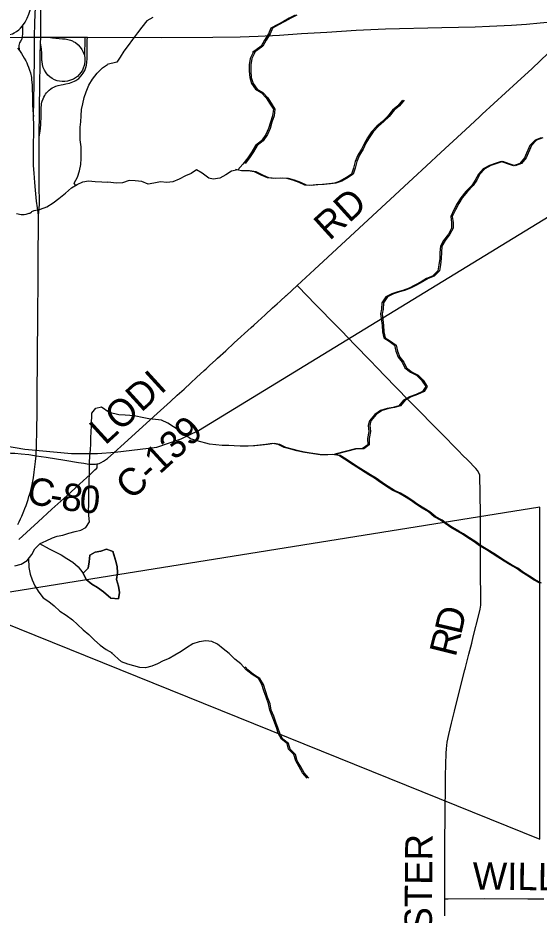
# Model space of a CAD drawing. Extents: x 0 to 34, y 0 to 22.
# Drawn here: x 16.545 to 17.627, y 4.394 to 6.258 of the extents above; entities that cross this region are included whole.
import ezdxf

# ---------------------------------------------------------------- set-up
doc = ezdxf.new("R2010")
doc.units = 0
for name, color, linetype in [('GM_X_County_Road', 7, 'Continuous'), ('GM_X_County_Road_Text', 7, 'Continuous'), ('GM_X_Interchange_Ramps', 7, 'Continuous'), ('GM_X_Minor_Lake', 7, 'Continuous'), ('GM_X_Minor_River', 7, 'Continuous'), ('GM_X_Rail_Line', 7, 'Continuous'), ('GM_X_State_Route', 7, 'Continuous'), ('GM_X_Township_Road', 7, 'Continuous'), ('GM_X_US_Route', 7, 'Continuous'), ('SH_Text', 7, 'Continuous')]:
    doc.layers.add(name, color=color, linetype=linetype)

msp = doc.modelspace()

# ---------------------------------------------------------------- linework, layer by layer
at = {"layer": 'GM_X_County_Road'}
for points in [[(16.7092, 5.3311), (16.7113, 5.3316), (16.7141, 5.3323), (16.7184, 5.334), (16.7231, 5.3366), (16.7312, 5.3422), (16.7447, 5.3541), (16.7661, 5.3736), (16.8274, 5.4295), (16.8621, 5.4611), (16.876, 5.4739), (16.8901, 5.4867), (16.9046, 5.4999), (16.916, 5.5106), (16.9318, 5.5251), (16.936, 5.5289), (16.943, 5.5354), (16.956, 5.5473), (16.9597, 5.5507), (16.9769, 5.5665), (16.9945, 5.5826), (17.0294, 5.6146), (17.0351, 5.6198), (17.0434, 5.6274), (17.0586, 5.6413), (17.0742, 5.6555), (17.0833, 5.6638), (17.0896, 5.6696), (17.1025, 5.6813), (17.1026, 5.6814), (17.1248, 5.7017), (17.1613, 5.7354), (17.328, 5.8895), (17.357, 5.9165), (17.3655, 5.9243), (17.3938, 5.9506), (17.4233, 5.9781), (17.4664, 6.0178), (17.4744, 6.0254), (17.5038, 6.0526), (17.5075, 6.0561), (17.5093, 6.0578), (17.5822, 6.1241), (17.613, 6.153), (17.6461, 6.1845)], [(17.4319, 4.3926), (17.4316, 4.4276), (17.4314, 4.4834), (17.432, 4.5583), (17.4325, 4.5866), (17.4333, 4.6832), (17.4337, 4.7064), (17.4344, 4.7303), (17.4349, 4.7393), (17.4363, 4.7529), (17.4398, 4.7689), (17.4455, 4.7925), (17.4517, 4.8174), (17.4735, 4.9041), (17.4737, 4.9047), (17.4746, 4.908), (17.4818, 4.9362), (17.4875, 4.9587), (17.4909, 4.9721), (17.5022, 5.0177), (17.505, 5.0297), (17.5065, 5.038), (17.5068, 5.0446), (17.5061, 5.113), (17.5059, 5.1526), (17.5055, 5.2282), (17.5043, 5.3077), (17.5022, 5.3124), (17.4995, 5.3175), (17.4964, 5.3214), (17.4794, 5.3388), (17.4687, 5.3495), (17.4609, 5.3577), (17.4533, 5.3654), (17.4303, 5.3888), (17.4132, 5.4063), (17.4, 5.4196), (17.3862, 5.4337), (17.358, 5.4625), (17.3301, 5.4909), (17.3075, 5.5138), (17.291, 5.531), (17.2766, 5.546), (17.2447, 5.5789), (17.217, 5.6077), (17.1973, 5.6275), (17.1735, 5.6518), (17.1612, 5.6647), (17.1475, 5.6788), (17.1248, 5.7017)], [(16.5831, 5.3482), (16.6041, 5.3452), (16.6424, 5.3391), (16.6709, 5.3345), (16.6821, 5.3327), (16.6927, 5.331), (16.6967, 5.3308), (16.7032, 5.3305), (16.7066, 5.3307), (16.7092, 5.3311)], [(17.4316, 4.4276), (17.4386, 4.4276), (17.5145, 4.4286), (17.6039, 4.4277), (17.6373, 4.4274)]]:
    msp.add_lwpolyline(points, dxfattribs=at)
at = {"layer": 'GM_X_Interchange_Ramps'}
for points in [[(16.5548, 6.2413), (16.5546, 6.2336), (16.5544, 6.226), (16.5542, 6.2176)], [(16.5542, 6.2176), (16.5539, 6.2163), (16.5534, 6.215), (16.553, 6.214), (16.5523, 6.2128), (16.5516, 6.2116), (16.5506, 6.2099), (16.5496, 6.2079), (16.5487, 6.2058), (16.548, 6.2036), (16.5474, 6.2006), (16.5474, 6.1987), (16.5474, 6.1966), (16.5478, 6.194), (16.5481, 6.1913), (16.5483, 6.1902)], [(16.5895, 6.01), (16.5915, 6.0226), (16.5925, 6.0357), (16.5934, 6.0549), (16.5938, 6.0727), (16.5941, 6.0761), (16.5945, 6.0797), (16.5952, 6.0827), (16.5958, 6.0852), (16.5976, 6.0899), (16.599, 6.093), (16.6008, 6.0965), (16.6026, 6.0993), (16.6048, 6.1022), (16.6073, 6.1052), (16.6098, 6.1075), (16.6134, 6.1103), (16.6166, 6.1124), (16.6197, 6.114), (16.6242, 6.116), (16.6289, 6.1174), (16.6347, 6.1188), (16.6394, 6.1197), (16.645, 6.1208), (16.6522, 6.1226), (16.656, 6.1238), (16.6594, 6.125), (16.6628, 6.1266), (16.6657, 6.1281), (16.6714, 6.1322), (16.6762, 6.1372), (16.6805, 6.1428), (16.684, 6.1488), (16.6863, 6.1547), (16.6875, 6.1595), (16.6885, 6.1658), (16.6887, 6.1728), (16.6889, 6.1953), (16.6892, 6.2072), (16.6893, 6.2118), (16.6895, 6.2177)], [(16.6841, 6.2176), (16.684, 6.2038), (16.6836, 6.1899), (16.6833, 6.1806)], [(16.5446, 6.195), (16.5483, 6.1902), (16.5525, 6.1838), (16.5554, 6.1793), (16.5585, 6.174), (16.5614, 6.1687), (16.5635, 6.1644), (16.5653, 6.1602), (16.5673, 6.1553), (16.5694, 6.1492), (16.571, 6.1436), (16.5731, 6.1342), (16.5737, 6.1294), (16.5742, 6.1244), (16.5748, 6.1178), (16.5751, 6.1096), (16.5754, 6.0962), (16.5756, 6.0779), (16.5764, 6.0654), (16.5778, 6.0532)]]:
    msp.add_lwpolyline(points, dxfattribs=at)
at = {"layer": 'GM_X_Minor_Lake'}
for points in [[(16.7423, 5.1496), (16.7294, 5.154), (16.7172, 5.1501), (16.7053, 5.1476), (16.6946, 5.1414), (16.6932, 5.1277), (16.6914, 5.1148), (16.6806, 5.1044), (16.6872, 5.0913), (16.6984, 5.0816), (16.7105, 5.0742), (16.7229, 5.0656), (16.7383, 5.0523)], [(16.7373, 5.0532), (16.7229, 5.0656), (16.7105, 5.0742), (16.6984, 5.0816), (16.6872, 5.0913), (16.6806, 5.1044), (16.6914, 5.1148), (16.6932, 5.1277), (16.6946, 5.1414), (16.7053, 5.1476), (16.7172, 5.1501), (16.7294, 5.154), (16.7412, 5.15)], [(16.7422, 5.1498), (16.7481, 5.1313), (16.7515, 5.1184), (16.752, 5.1047), (16.7501, 5.0911), (16.754, 5.077), (16.7559, 5.0641), (16.7541, 5.0512), (16.7377, 5.0524)], [(16.7383, 5.0523), (16.7541, 5.0512), (16.7559, 5.0641), (16.754, 5.077), (16.7501, 5.0911), (16.752, 5.1047), (16.7515, 5.1184), (16.7481, 5.1313), (16.7423, 5.1496)]]:
    msp.add_lwpolyline(points, dxfattribs=at)
at = {"layer": 'GM_X_Minor_River'}
for points in [[(17.1212, 6.2636), (17.1087, 6.2575), (17.0966, 6.2502), (17.0833, 6.2437), (17.0704, 6.2369), (17.0658, 6.2251), (17.0575, 6.2114), (17.0503, 6.1992), (17.0326, 6.1862)], [(17.1245, 6.2636), (17.112, 6.2575), (17.0998, 6.2502), (17.0865, 6.2437), (17.0736, 6.2369), (17.0691, 6.2251), (17.0608, 6.2114), (17.0536, 6.1992), (17.0359, 6.1862)], [(16.8256, 6.259), (16.8127, 6.2521), (16.8025, 6.2384), (16.7934, 6.2266), (16.7828, 6.2133), (16.7741, 6.2007), (16.765, 6.1886), (16.7574, 6.176), (16.7506, 6.1657), (16.7305, 6.161)], [(17.0336, 6.1859), (17.0276, 6.1733), (17.0254, 6.1604), (17.0254, 6.1475), (17.0266, 6.1338), (17.0305, 6.1213), (17.0385, 6.1095), (17.0503, 6.1031), (17.061, 6.0921), (17.0679, 6.0804), (17.0756, 6.0682), (17.0737, 6.0545), (17.0696, 6.0412), (17.0658, 6.0283), (17.0602, 6.0154), (17.0511, 6.0028), (17.0389, 5.9929), (17.031, 5.9796), (17.0227, 5.967), (17.0124, 5.9541), (17.0018, 5.9423), (16.9889, 5.9396), (16.9768, 5.932), (16.9642, 5.9251), (16.9509, 5.9231), (16.9414, 5.9246), (16.9281, 5.9356), (16.9162, 5.9424), (16.9048, 5.9344), (16.8931, 5.9298), (16.8802, 5.9226), (16.8672, 5.9172), (16.8547, 5.9157), (16.8414, 5.9172), (16.8277, 5.9148), (16.8155, 5.9125), (16.8026, 5.9178), (16.7889, 5.9197), (16.7759, 5.92), (16.7626, 5.9154), (16.7497, 5.9146), (16.7321, 5.9163)], [(17.0369, 6.1859), (17.0309, 6.1733), (17.0286, 6.1604), (17.0287, 6.1475), (17.0299, 6.1338), (17.0337, 6.1213), (17.0418, 6.1095), (17.0536, 6.1031), (17.0643, 6.0921), (17.0712, 6.0804), (17.0788, 6.0682), (17.077, 6.0545), (17.0728, 6.0412), (17.0691, 6.0283), (17.0634, 6.0154), (17.0543, 6.0028), (17.0422, 5.9929), (17.0343, 5.9796), (17.0259, 5.967), (17.0169, 5.9556)], [(16.6649, 5.9106), (16.6623, 5.9145), (16.669, 5.9273), (16.6734, 5.9405), (16.6759, 5.9534), (16.6765, 5.9655), (16.6764, 5.9784), (16.6762, 5.9902), (16.6746, 6.0043), (16.6744, 6.0173), (16.6747, 6.0309), (16.6756, 6.0423), (16.6762, 6.0545), (16.6772, 6.0674), (16.6797, 6.0795), (16.6826, 6.0924), (16.6866, 6.1045), (16.6922, 6.118), (16.7004, 6.1308), (16.7098, 6.1428), (16.721, 6.154), (16.7309, 6.1611)], [(17.3437, 6.0872), (17.3343, 6.075), (17.3233, 6.0659), (17.3127, 6.0533), (17.302, 6.0426), (17.2907, 6.0327), (17.2793, 6.0213), (17.2714, 6.0087), (17.2646, 5.9973), (17.2589, 5.9852), (17.2509, 5.973), (17.2457, 5.9593), (17.2419, 5.9456), (17.2382, 5.9331), (17.2275, 5.9262), (17.2146, 5.9189), (17.2025, 5.9143), (17.1911, 5.9132), (17.1777, 5.912), (17.1648, 5.9108), (17.1511, 5.9096), (17.1412, 5.9104), (17.1294, 5.916), (17.1161, 5.9206), (17.1035, 5.9239), (17.0906, 5.9251), (17.0769, 5.9243), (17.0632, 5.9257), (17.0502, 5.931), (17.0365, 5.9378), (17.0228, 5.9401), (17.0098, 5.9404), (16.9969, 5.943)], [(17.347, 6.0872), (17.3375, 6.075), (17.3265, 6.0659), (17.3159, 6.0533), (17.3053, 6.0426), (17.2939, 6.0327), (17.2826, 6.0213), (17.2746, 6.0087), (17.2678, 5.9973), (17.2622, 5.9852), (17.2542, 5.973), (17.2489, 5.9593), (17.2452, 5.9456), (17.2414, 5.9331), (17.2308, 5.9262), (17.2179, 5.9189), (17.2057, 5.9143), (17.1943, 5.9132), (17.181, 5.912), (17.1681, 5.9108), (17.1544, 5.9096), (17.1445, 5.9104), (17.1327, 5.916), (17.1193, 5.9206), (17.1068, 5.9239), (17.0938, 5.9251), (17.0801, 5.9243), (17.0664, 5.9257), (17.0535, 5.931), (17.0397, 5.9378), (17.026, 5.9401), (17.0169, 5.9403)], [(17.6321, 6.0086), (17.6191, 6.0036), (17.6085, 5.9929), (17.5972, 5.9671), (17.5877, 5.9557), (17.5744, 5.9507), (17.5619, 5.9548), (17.5489, 5.9594), (17.5364, 5.9551), (17.5242, 5.9509), (17.5113, 5.9444), (17.5015, 5.9334), (17.495, 5.9205), (17.4875, 5.9094), (17.4753, 5.8972), (17.4647, 5.8843), (17.4575, 5.8721), (17.4507, 5.8592), (17.4439, 5.8455), (17.4455, 5.8326), (17.4456, 5.8208), (17.4391, 5.8086), (17.4293, 5.7953), (17.4225, 5.7835), (17.4214, 5.7702), (17.4211, 5.758), (17.4196, 5.7451), (17.4174, 5.7326), (17.406, 5.7215), (17.3938, 5.7162), (17.3824, 5.7097), (17.3695, 5.7024), (17.3574, 5.6967), (17.3445, 5.6917), (17.3342, 5.6887), (17.3217, 5.6845), (17.3095, 5.6787), (17.3012, 5.6658), (17.3001, 5.6525), (17.2982, 5.643), (17.3014, 5.6187), (17.3022, 5.6058), (17.3049, 5.5929), (17.3159, 5.5864), (17.3274, 5.5777), (17.3301, 5.5652), (17.3347, 5.5531), (17.3431, 5.5428), (17.3485, 5.5307), (17.3607, 5.5216), (17.3729, 5.5156), (17.3832, 5.505), (17.392, 5.4921), (17.3856, 5.4814), (17.3719, 5.4753), (17.3582, 5.4707), (17.3461, 5.4638), (17.3362, 5.4516), (17.3241, 5.4482), (17.3123, 5.4463), (17.2982, 5.4424), (17.2861, 5.4337), (17.2751, 5.4207), (17.2728, 5.4112), (17.274, 5.3983), (17.2714, 5.3842), (17.2715, 5.3709), (17.2601, 5.3629), (17.2464, 5.3629), (17.2033, 5.3513)], [(17.6353, 6.0086), (17.6224, 6.0036), (17.6118, 5.9929), (17.6005, 5.9671), (17.591, 5.9557), (17.5777, 5.9507), (17.5651, 5.9548), (17.5522, 5.9594), (17.5396, 5.9551), (17.5275, 5.9509), (17.5146, 5.9444), (17.5047, 5.9334), (17.4983, 5.9205), (17.4907, 5.9094), (17.4786, 5.8972), (17.468, 5.8843), (17.4608, 5.8721), (17.454, 5.8592), (17.4472, 5.8455), (17.4488, 5.8326), (17.4488, 5.8208), (17.4424, 5.8086), (17.4326, 5.7953), (17.4258, 5.7835), (17.4247, 5.7702), (17.4243, 5.758), (17.4229, 5.7451), (17.4206, 5.7326), (17.4093, 5.7215), (17.3971, 5.7162), (17.3857, 5.7097), (17.3728, 5.7024), (17.3606, 5.6967), (17.3477, 5.6917), (17.3375, 5.6887), (17.3249, 5.6845), (17.3128, 5.6787), (17.3044, 5.6658), (17.3034, 5.6525), (17.3015, 5.643), (17.3046, 5.6187), (17.3054, 5.6058), (17.3081, 5.5929), (17.3192, 5.5864), (17.3307, 5.5777), (17.3334, 5.5652), (17.338, 5.5531), (17.3464, 5.5428), (17.3518, 5.5307), (17.364, 5.5216), (17.3762, 5.5156), (17.3865, 5.505), (17.3953, 5.4921), (17.3888, 5.4814), (17.3752, 5.4753), (17.3615, 5.4707), (17.3493, 5.4638), (17.3395, 5.4516), (17.3273, 5.4482), (17.3155, 5.4463), (17.3015, 5.4424), (17.2893, 5.4337), (17.2784, 5.4207), (17.2761, 5.4112), (17.2773, 5.3983), (17.2747, 5.3842), (17.2747, 5.3709), (17.2633, 5.3629), (17.2497, 5.3629), (17.2065, 5.3513)], [(16.5787, 5.8575), (16.5924, 5.8607), (16.6055, 5.8657), (16.6186, 5.8735), (16.6305, 5.8828), (16.6437, 5.8935), (16.6564, 5.9047), (16.668, 5.9121), (16.6803, 5.9175), (16.6921, 5.9196), (16.7058, 5.9182), (16.7195, 5.9176), (16.7316, 5.9168)], [(16.542, 5.8514), (16.5454, 5.8509), (16.5485, 5.8501), (16.5519, 5.8493), (16.5553, 5.8492), (16.558, 5.8495), (16.5622, 5.8502), (16.5645, 5.8509), (16.5687, 5.852), (16.5702, 5.8524), (16.5721, 5.8535), (16.5737, 5.8542), (16.5744, 5.8557), (16.5791, 5.8577)], [(16.5388, 5.1196), (16.5522, 5.1228), (16.5642, 5.1306), (16.5739, 5.1429), (16.5802, 5.1546), (16.5914, 5.1658), (16.6037, 5.1712), (16.6168, 5.1775), (16.6267, 5.1814), (16.6386, 5.1831), (16.6508, 5.1871), (16.6638, 5.1906), (16.6761, 5.1938), (16.6864, 5.1993), (16.6935, 5.211), (16.6926, 5.2239), (16.692, 5.2342), (16.6922, 5.246), (16.6928, 5.2555), (16.6926, 5.2653), (16.6928, 5.2783), (16.6934, 5.2881), (16.6932, 5.2976), (16.6938, 5.3102), (16.694, 5.322), (16.6938, 5.3345), (16.6948, 5.3474), (16.6962, 5.3603), (16.6964, 5.3729), (16.6963, 5.3862), (16.6972, 5.3975), (16.6982, 5.4108), (16.6987, 5.4367), (16.7069, 5.4472), (16.7191, 5.4496), (16.7345, 5.4385)], [(17.6291, 5.0832), (17.6161, 5.0904), (17.6047, 5.098), (17.5921, 5.1055), (17.5802, 5.1146), (17.5673, 5.1214), (17.5547, 5.129), (17.5421, 5.1373), (17.5299, 5.1452), (17.5181, 5.1524), (17.504, 5.1611), (17.4925, 5.1691), (17.4796, 5.1778), (17.467, 5.1857), (17.4574, 5.1918), (17.4445, 5.1993), (17.4323, 5.2073), (17.4227, 5.2141), (17.4098, 5.2216), (17.3976, 5.2319), (17.3846, 5.239), (17.3728, 5.2466), (17.3602, 5.2561), (17.348, 5.2636), (17.3365, 5.2704), (17.3239, 5.2761), (17.3106, 5.2844), (17.2984, 5.2924), (17.2858, 5.3018), (17.274, 5.3086), (17.2488, 5.3245), (17.2358, 5.3325), (17.2236, 5.3408), (17.2114, 5.3487), (17.1985, 5.351), (17.1856, 5.3502), (17.173, 5.3501), (17.1593, 5.3524), (17.1498, 5.3535), (17.1368, 5.3557), (17.1246, 5.3584), (17.1117, 5.3621), (17.0984, 5.3655), (17.0858, 5.3716), (17.074, 5.3734), (17.0603, 5.3719), (17.0477, 5.3703), (17.0341, 5.3688), (17.0204, 5.368), (17.0067, 5.3683), (16.9945, 5.369), (16.9831, 5.3694), (16.9694, 5.3693), (16.9564, 5.3708), (16.9427, 5.3723), (16.9176, 5.3791), (16.9039, 5.3836), (16.8905, 5.3927), (16.8779, 5.4021), (16.868, 5.4086), (16.8562, 5.4161), (16.8432, 5.4218), (16.8307, 5.4237), (16.8173, 5.4248), (16.8033, 5.4274), (16.7899, 5.4304), (16.7774, 5.4315), (16.7679, 5.4322), (16.7549, 5.433), (16.7349, 5.4381)], [(17.6323, 5.0832), (17.6194, 5.0904), (17.6079, 5.098), (17.5953, 5.1055), (17.5835, 5.1146), (17.5705, 5.1214), (17.558, 5.129), (17.5454, 5.1373), (17.5332, 5.1452), (17.5213, 5.1524), (17.5072, 5.1611), (17.4958, 5.1691), (17.4828, 5.1778), (17.4702, 5.1857), (17.4607, 5.1918), (17.4477, 5.1993), (17.4355, 5.2073), (17.426, 5.2141), (17.413, 5.2216), (17.4008, 5.2319), (17.3879, 5.239), (17.376, 5.2466), (17.3634, 5.2561), (17.3512, 5.2636), (17.3398, 5.2704), (17.3272, 5.2761), (17.3139, 5.2844), (17.3017, 5.2924), (17.2891, 5.3018), (17.2773, 5.3086), (17.2521, 5.3245), (17.2391, 5.3325), (17.2269, 5.3408), (17.2147, 5.3487), (17.2018, 5.351), (17.1888, 5.3502), (17.1763, 5.3501), (17.1626, 5.3524), (17.153, 5.3535), (17.1401, 5.3557), (17.1279, 5.3584), (17.115, 5.3621), (17.1016, 5.3655), (17.0891, 5.3716), (17.0773, 5.3734), (17.0636, 5.3719), (17.051, 5.3703), (17.0373, 5.3688), (17.0236, 5.368), (17.0169, 5.3681)], [(16.5901, 5.1661), (16.6103, 5.1551), (16.6223, 5.1485), (16.6348, 5.1425), (16.6468, 5.1347), (16.6593, 5.1268), (16.6705, 5.1175), (16.6802, 5.105)], [(16.5672, 5.1348), (16.5681, 5.1157), (16.5705, 5.1023), (16.5749, 5.0904), (16.5803, 5.0778), (16.5885, 5.0647), (16.5978, 5.0527), (16.6091, 5.0457), (16.6207, 5.0367), (16.6323, 5.0255), (16.6451, 5.0169), (16.6583, 5.0075), (16.6691, 4.9978), (16.6807, 4.9862), (16.6928, 4.9768), (16.7043, 4.9652), (16.7163, 4.9547), (16.7287, 4.9457), (16.7408, 4.939)], [(17.1458, 4.6781), (17.1363, 4.6895), (17.1294, 4.702), (17.1221, 4.7145), (17.1183, 4.7274), (17.1072, 4.7388), (17.1041, 4.7505), (17.0923, 4.7596), (17.0858, 4.7721), (17.0827, 4.7816), (17.0777, 4.7949), (17.0734, 4.8074), (17.0681, 4.8199), (17.0657, 4.8329), (17.0604, 4.8465), (17.0557, 4.8598), (17.0519, 4.8727), (17.0446, 4.8852), (17.0313, 4.8939), (17.0191, 4.9034), (17.008, 4.9159), (16.9954, 4.9257), (16.9839, 4.9371), (16.9713, 4.9473), (16.9595, 4.9564), (16.9477, 4.9621), (16.9351, 4.9639), (16.9214, 4.9616), (16.9081, 4.9574), (16.8956, 4.949), (16.8842, 4.9418), (16.8713, 4.9341), (16.8595, 4.9269), (16.847, 4.9223), (16.8352, 4.9158), (16.8235, 4.9112), (16.8098, 4.9077), (16.7984, 4.9085), (16.7862, 4.9119), (16.7736, 4.9149), (16.7606, 4.9201), (16.7385, 4.9397)], [(17.1491, 4.6781), (17.1396, 4.6895), (17.1327, 4.702), (17.1254, 4.7145), (17.1215, 4.7274), (17.1105, 4.7388), (17.1074, 4.7505), (17.0955, 4.7596), (17.089, 4.7721), (17.0859, 4.7816), (17.0809, 4.7949), (17.0767, 4.8074), (17.0713, 4.8199), (17.069, 4.8329), (17.0636, 4.8465), (17.059, 4.8598), (17.0552, 4.8727), (17.0479, 4.8852), (17.0345, 4.8939), (17.0223, 4.9034), (17.0169, 4.9095)]]:
    msp.add_lwpolyline(points, dxfattribs=at)
at = {"layer": 'GM_X_Rail_Line'}
msp.add_lwpolyline([(15.8135, 5.4605), (15.8139, 5.4606), (15.8872, 5.4674), (15.9697, 5.4605), (16.1438, 5.433), (16.5597, 5.3622), (16.6563, 5.3532), (16.7102, 5.353), (16.747, 5.3555), (16.8335, 5.3663), (16.8845, 5.3834), (16.9205, 5.4007), (17.7478, 5.9072), (18.0934, 6.1301), (18.2278, 6.215)], dxfattribs=at)
at = {"layer": 'GM_X_State_Route'}
msp.add_lwpolyline([(16.6081, 6.2177), (16.6841, 6.2176), (16.6895, 6.2177), (16.843, 6.2174), (16.9499, 6.2177), (17.0064, 6.2186), (17.044, 6.2198), (17.0881, 6.2221), (17.1338, 6.2252), (17.1868, 6.2286), (17.2478, 6.2323), (17.3088, 6.2355), (17.4256, 6.2377), (17.4945, 6.2392), (17.5242, 6.2409), (17.5702, 6.2429), (17.6014, 6.245), (17.6295, 6.2476), (17.6599, 6.2504), (17.6778, 6.2519), (17.6901, 6.2526), (17.6989, 6.2527), (17.7057, 6.2525)], dxfattribs=at)
at = {"layer": 'GM_X_Township_Road'}
for points in [[(16.4526, 5.3542), (16.4758, 5.3543), (16.521, 5.3541), (16.5305, 5.3538), (16.5386, 5.3534), (16.5517, 5.3525), (16.5676, 5.3508), (16.5794, 5.3488), (16.5831, 5.3482)], [(16.5471, 5.1745), (16.5869, 5.2107), (16.6158, 5.2369), (16.6403, 5.2594), (16.6558, 5.2733), (16.6734, 5.2895), (16.6962, 5.3102), (16.705, 5.3187), (16.7089, 5.3225), (16.7096, 5.3242), (16.7099, 5.3258), (16.7097, 5.3286), (16.7092, 5.3311)]]:
    msp.add_lwpolyline(points, dxfattribs=at)
at = {"layer": 'GM_X_US_Route'}
msp.add_line((16.5924, 6.2056), (16.5926, 6.2174), dxfattribs=at)
for points in [[(16.5926, 6.2178), (16.5931, 6.3504)], [(16.4814, 6.2175), (16.4906, 6.2197), (16.4998, 6.2211), (16.5113, 6.2218), (16.5218, 6.2225), (16.5277, 6.2233), (16.5336, 6.2249), (16.5377, 6.2269), (16.5422, 6.2297), (16.5468, 6.2331), (16.5509, 6.2368), (16.5548, 6.2413), (16.56, 6.2491), (16.5642, 6.2576), (16.5676, 6.2654), (16.5712, 6.2757), (16.5736, 6.2838)], [(16.5796, 6.2059), (16.5798, 6.2176), (16.5803, 6.2481), (16.5815, 6.2801)], [(16.4784, 6.2175), (16.4814, 6.2175), (16.5542, 6.2176), (16.5798, 6.2176), (16.5925, 6.2176), (16.6081, 6.2177)], [(16.6582, 6.21), (16.6601, 6.2092), (16.6648, 6.2066), (16.6703, 6.2021), (16.6748, 6.1969), (16.6781, 6.1921), (16.6808, 6.1869), (16.6833, 6.1806), (16.6843, 6.1741), (16.6839, 6.1669), (16.6829, 6.1593), (16.6808, 6.1537), (16.679, 6.1494), (16.6762, 6.1449), (16.6727, 6.14), (16.6692, 6.1364), (16.6649, 6.1332), (16.6604, 6.1307), (16.6544, 6.1282), (16.6483, 6.1266), (16.6427, 6.1258), (16.6372, 6.1255), (16.6316, 6.1262), (16.6268, 6.1273), (16.6215, 6.1292), (16.6161, 6.1322), (16.6115, 6.1353), (16.6073, 6.139), (16.6036, 6.1437), (16.6001, 6.1492), (16.5977, 6.1551), (16.5961, 6.1613), (16.5953, 6.1674), (16.5952, 6.1696)], [(16.6081, 6.2177), (16.6171, 6.2164), (16.6376, 6.2147), (16.6431, 6.2142), (16.6487, 6.2133), (16.6544, 6.2116), (16.6582, 6.21)], [(16.5792, 6.1347), (16.5793, 6.1689), (16.5796, 6.2059)], [(16.5913, 6.1596), (16.5915, 6.1784), (16.5924, 6.2056)], [(16.5952, 6.1696), (16.595, 6.1739), (16.5948, 6.184), (16.5943, 6.1938), (16.5924, 6.2056)], [(16.5898, 5.8802), (16.5895, 5.9032), (16.5894, 5.9706), (16.5895, 6.01), (16.5908, 6.122), (16.5913, 6.1596)], [(16.5882, 5.8479), (16.5857, 5.8632), (16.5841, 5.8771), (16.5819, 5.9), (16.5803, 5.9159), (16.5789, 5.9356), (16.5779, 5.9512), (16.5777, 5.9802), (16.578, 6.0342), (16.5778, 6.0532), (16.5791, 6.1216), (16.5792, 6.1347)], [(16.5831, 5.3482), (16.5837, 5.3695), (16.5842, 5.4), (16.5849, 5.4392), (16.5852, 5.4721), (16.5858, 5.5529), (16.5861, 5.5832), (16.5864, 5.6094), (16.5867, 5.638), (16.5872, 5.7158), (16.5875, 5.7437), (16.5882, 5.8479), (16.5895, 5.8608), (16.5899, 5.8722), (16.5898, 5.8802)], [(16.5451, 5.2053), (16.5479, 5.2111), (16.5506, 5.2169), (16.5533, 5.2228), (16.5575, 5.2328), (16.5598, 5.2388), (16.5621, 5.2449), (16.5642, 5.251), (16.5663, 5.2571), (16.5682, 5.2632), (16.57, 5.2694), (16.5717, 5.2756), (16.5733, 5.2819), (16.5748, 5.2882), (16.5775, 5.3026), (16.5791, 5.3141), (16.5818, 5.3361), (16.5831, 5.3482)]]:
    msp.add_lwpolyline(points, dxfattribs=at)
at = {"layer": 'SH_Text'}
msp.add_lwpolyline([(17.6287, 5.2416), (16.4069, 5.0452), (17.6287, 4.5513)], close=True, dxfattribs=at)

# ---------------------------------------------------------------- texts
at = {"layer": 'GM_X_County_Road_Text'}
for s, height, rotation, p in [('RD', 0.05682, 42.2068, (17.1923, 5.7937)), ('LODI', 0.05682, 42.3511, (16.7264, 5.3687)), ('C-139', 0.05682, 42.4594, (16.7806, 5.2543)), ('C', 0.0568, 348.4792, (16.5611, 5.2505)), ('8', 0.0568, 351.5609, (16.6332, 5.2368)), ('0', 0.0568, 354.8876, (16.6714, 5.2312)), ('-', 0.0568, 350.5362, (16.6091, 5.2408)), ('D', 0.0568, 76.9615, (17.4655, 4.9747)), ('R', 0.0568, 75.9751, (17.454, 4.9284)), ('FRANCHESTER', 0.056818, 89.5163, (17.4016, 3.9922)), ('WILLOW', 0.05682, 359.3425, (17.4893, 4.447))]:
    msp.add_text(s, height=height, rotation=rotation, dxfattribs=at).set_placement(p)

doc.saveas('drawing.dxf')
